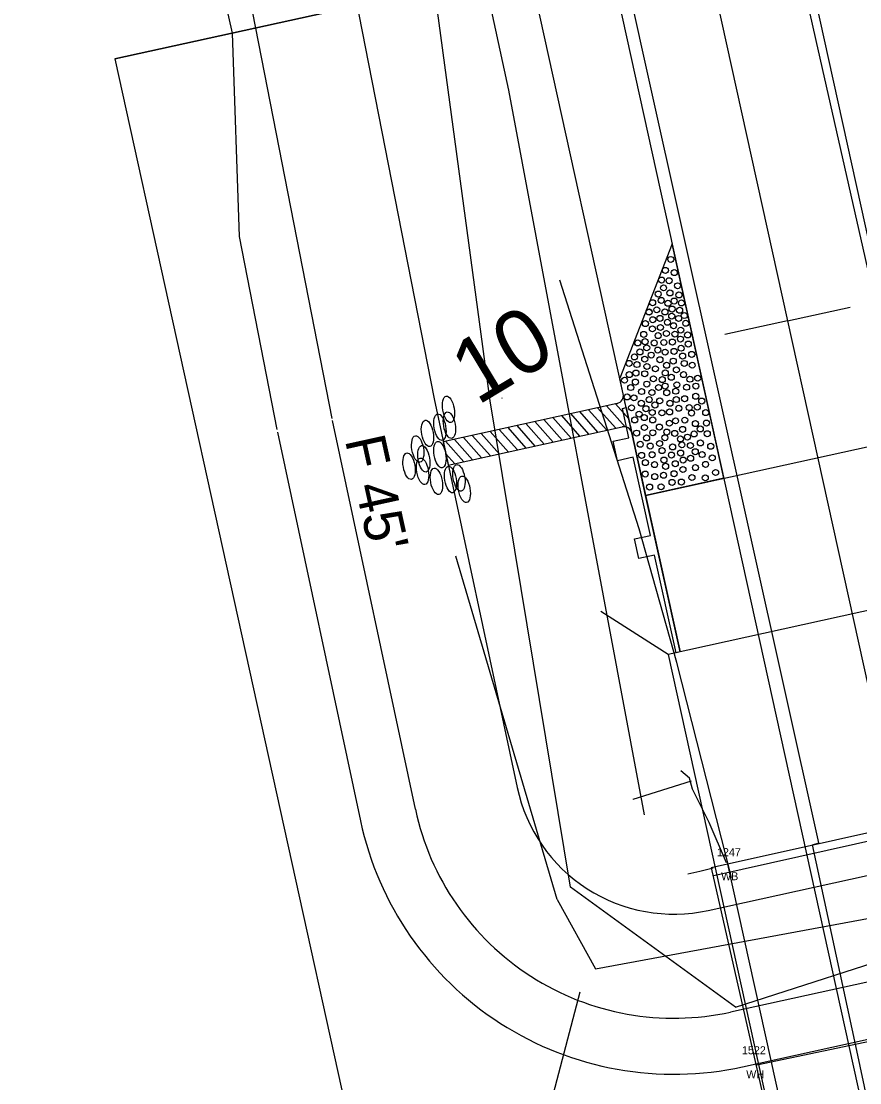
# Model space of a CAD drawing. Extents: x 2519952 to 2531965, y 848341 to 887632.
# Drawn here: x 2530852.7 to 2530957.4, y 852514.8 to 852647.4 of the extents above; entities that cross this region are included whole.
import ezdxf

# ---------------------------------------------------------------- set-up
doc = ezdxf.new("R2010")
doc.units = 0
for name, color, linetype in [('RD_EV_JW', 7, 'Continuous'), ('RD_EX_BldgApp', 7, 'Continuous'), ('RD_EX_BldgApp_txCode', 7, 'Continuous'), ('RD_EX_Bridge', 7, 'Continuous'), ('RD_EX_Conc', 7, 'Continuous'), ('RD_EX_DR_Pipe', 7, 'Continuous'), ('RD_EX_DV_Prop', 7, 'Continuous'), ('RD_EX_GuardRail', 7, 'Continuous'), ('RD_EX_H2O', 7, 'Continuous'), ('RD_EX_Misc', 7, 'Continuous'), ('RD_EX_Road', 7, 'Continuous'), ('RD_EX_RW', 7, 'Continuous'), ('RD_EX_VEG', 7, 'Continuous'), ('RD_HC_Cl', 7, 'Continuous'), ('RD_HC_Data_Tic', 7, 'Continuous'), ('RD_HC_TX_Sta50', 7, 'Continuous'), ('RD_PD_BCA', 7, 'Continuous'), ('RD_PD_Bridge', 7, 'Continuous'), ('RD_PD_CstnLmt', 7, 'Continuous'), ('RD_PD_DR_ErosCtrl', 7, 'Continuous'), ('RD_PD_Final_TrvlWay', 7, 'Continuous'), ('RD_PD_GR', 7, 'Continuous'), ('RD_PD_PaveShd', 7, 'Continuous'), ('RD_PD_RW', 7, 'Continuous'), ('RD_SMD_Locator', 7, 'Continuous')]:
    doc.layers.add(name, color=color, linetype=linetype)

# ---------------------------------------------------------------- blocks, each defined once
blk = doc.blocks.new('TBC1')
at = {"layer": 'RD_PD_GR'}
blk.add_lwpolyline([(12.5, 2.5), (15, 2.5), (15, 0.49), (25, 0.49), (25, 2.5), (27.5, 2.5), (27.5, 0.49), (31.25, 0.49), (31.25, 0), (0, 0), (0, 0.49), (12.5, 0.49)], close=True, dxfattribs=at)

msp = doc.modelspace()

# ---------------------------------------------------------------- linework, layer by layer
at = {"layer": 'RD_EV_JW'}
for points in [[(2530941.93, 852524.2), (2530921.34, 852539.21), (2530911.31, 852599.95), (2530891.36, 852747.65), (2530878.86, 852801.36), (2530855.69, 852888.8), (2530838.36, 852954.41), (2530821.58, 853001.04), (2530764.42, 853117.09), (2530719.97, 853083.34), (2530675.19, 853037.15)], [(2530941.93, 852524.2), (2530988.97, 852539.38), (2531002.68, 852568.81), (2530983.61, 852626.72), (2530958.57, 852695.74), (2530928.96, 852834.5), (2530911.44, 852907.05), (2530889.4, 853007.47), (2530879.48, 853052.19), (2530908.59, 853055.99), (2530938.06, 853061.93)]]:
    msp.add_lwpolyline(points, dxfattribs=at)
at = {"layer": 'RD_EX_BldgApp'}
msp.add_lwpolyline([(2530957.44, 852468.09), (2530949.04, 852505.48), (2530940.97, 852542.07)], dxfattribs=at)
at = {"layer": 'RD_EX_Bridge'}
for points in [[(2530955.67, 852467.77), (2531001.96, 852478), (2530985.83, 852552.07), (2530938.91, 852541.61), (2530955.67, 852467.77)], [(2530939.14, 852541.57), (2530937.47, 852541.16), (2530935.99, 852540.81)]]:
    msp.add_lwpolyline(points, dxfattribs=at)
at = {"layer": 'RD_EX_Conc'}
msp.add_lwpolyline([(2530940.81, 852542.25), (2530938.66, 852547.28), (2530936.57, 852551.45), (2530936.17, 852552.82), (2530935.11, 852553.74)], dxfattribs=at)
at = {"layer": 'RD_EX_DR_Pipe'}
msp.add_line((2530936.38, 852552.44), (2530929.1, 852550.16), dxfattribs=at)
at = {"layer": 'RD_EX_DV_Prop'}
for p, q in [((2530901.05, 852650.7), (2530864.42, 852642.64)), ((2530864.42, 852642.64), (2530928.94, 852349.66))]:
    msp.add_line(p, q, dxfattribs=at)
at = {"layer": 'RD_EX_GuardRail'}
for p, q in [((2530929.92, 852583.96), (2530920.01, 852615)), ((2530934.59, 852567.25), (2530929.92, 852583.96)), ((2530941.41, 852540.41), (2530934.59, 852567.25))]:
    msp.add_line(p, q, dxfattribs=at)
at = {"layer": 'RD_EX_H2O'}
msp.add_line((2530919.67, 852537.67), (2530907, 852580.53), dxfattribs=at)
for points in [[(2530919.67, 852537.67), (2530924.46, 852529.02), (2530997.12, 852542.46), (2531003.19, 852553.47), (2531007.69, 852596.79)], [(2530922.51, 852526.1), (2530912.95, 852489.75), (2530845.66, 852450.43), (2530795.63, 852412.19), (2530739.71, 852362.8), (2530741.39, 852332.59), (2530670.77, 852301.94)]]:
    msp.add_lwpolyline(points, dxfattribs=at)
at = {"layer": 'RD_EX_Misc'}
for p, q in [((2530939.22, 852540.64), (2530986.42, 852551.24)), ((2530991.48, 852526.75), (2530944.59, 852516.98))]:
    msp.add_line(p, q, dxfattribs=at)
at = {"layer": 'RD_EX_Road'}
for p, q in [((2530952, 852644.96), (2530932.11, 852735.09)), ((2530931.08, 852640.35), (2530910.78, 852730.8)), ((2530973.54, 852549.48), (2530952, 852644.96)), ((2530952.34, 852544.74), (2530931.08, 852640.35)), ((2530951.56, 852544.47), (2530952.34, 852544.74)), ((2530956.94, 852519.38), (2530951.56, 852544.47)), ((2530962.28, 852494.94), (2530956.94, 852519.38))]:
    msp.add_line(p, q, dxfattribs=at)
at = {"layer": 'RD_EX_RW'}
for q in [(2530901.05, 852650.7), (2530928.94, 852349.65)]:
    msp.add_line((2530864.42, 852642.64), q, dxfattribs=at)
at = {"layer": 'RD_EX_VEG'}
msp.add_lwpolyline([(2530930.57, 852548.23), (2530913.63, 852638.74), (2530872.38, 852829.12), (2530820.28, 852991.21)], dxfattribs=at)
at = {"layer": 'RD_HC_Cl'}
msp.add_line((2530821.93, 853184.38), (2531378.52, 850656.73), dxfattribs=at)
at = {"layer": 'RD_HC_Data_Tic'}
for q in [(2530956.24, 852611.65), (2530940.61, 852608.21)]:
    msp.add_line((2530948.42, 852609.93), q, dxfattribs=at)
at = {"layer": 'RD_PD_BCA'}
for p, q in [((2530879.07, 852645.86), (2530879.95, 852620.45)), ((2530879.95, 852620.45), (2530884.65, 852596.38)), ((2530884.72, 852596.03), (2530895.1, 852547.47))]:
    msp.add_line(p, q, dxfattribs=at)
msp.add_lwpolyline([(2530942.82, 852516.77), (2530991.6, 852527.51)], dxfattribs=at)
msp.add_arc((2530934.22, 852555.83), 40, 192.0677, 282.4185, dxfattribs=at)
at = {"layer": 'RD_PD_Bridge'}
for p, q in [((2530930.7, 852588.11), (2530973.67, 852597.58)), ((2530935, 852568.58), (2530930.7, 852588.11)), ((2530933.54, 852568.26), (2530925.11, 852573.65))]:
    msp.add_line(p, q, dxfattribs=at)
for points in [[(2530979.44, 852578.37), (2530933.54, 852568.26)], [(2530933.54, 852568.26), (2530961.49, 852441.3)]]:
    msp.add_lwpolyline(points, dxfattribs=at)
at = {"layer": 'RD_PD_CstnLmt'}
for p, q in [((2530885.11, 852698.39), (2530904.28, 852600.21)), ((2530904.28, 852600.21), (2530914.66, 852551.65))]:
    msp.add_line(p, q, dxfattribs=at)
msp.add_lwpolyline([(2530938.52, 852536.3), (2530987.3, 852547.04)], dxfattribs=at)
msp.add_arc((2530934.22, 852555.83), 20, 192.0677, 282.4185, dxfattribs=at)
at = {"layer": 'RD_PD_DR_ErosCtrl'}
for p, q in [((2530872.35, 852695.9), (2530891.52, 852597.72)), ((2530891.56, 852597.5), (2530901.94, 852548.93))]:
    msp.add_line(p, q, dxfattribs=at)
msp.add_lwpolyline([(2530941.31, 852523.61), (2530990.1, 852534.35)], dxfattribs=at)
msp.add_arc((2530934.22, 852555.83), 33, 192.0677, 282.4185, dxfattribs=at)
at = {"layer": 'RD_PD_Final_TrvlWay'}
for p, q in [((2530922.51, 852783.42), (2531196.7, 851538.25)), ((2530899.07, 852778.26), (2531173.26, 851533.09))]:
    msp.add_line(p, q, dxfattribs=at)
at = {"layer": 'RD_PD_GR'}
msp.add_line((2530928.28, 852599.1), (2530879.89, 852818.84), dxfattribs=at)
at = {"layer": 'RD_PD_PaveShd'}
for p, q in [((2530934.01, 852619.56), (2530927.47, 852602.76)), ((2530940.47, 852590.27), (2530934.01, 852619.56)), ((2530928.12, 852599.83), (2530927.47, 852602.76)), ((2530927.14, 852599.62), (2530905.43, 852594.82)), ((2530926.97, 852596.51), (2530924.7, 852599.08)), ((2530928.14, 852596.7), (2530925.82, 852599.33)), ((2530928.59, 852597.7), (2530926.93, 852599.57)), ((2530928.76, 852596.9), (2530928.12, 852599.83)), ((2530921.39, 852595.28), (2530919.12, 852597.85)), ((2530922.51, 852595.52), (2530920.23, 852598.09)), ((2530923.62, 852595.77), (2530921.35, 852598.34)), ((2530924.74, 852596.02), (2530922.47, 852598.59)), ((2530925.86, 852596.26), (2530923.58, 852598.83)), ((2530906.05, 852591.89), (2530927.79, 852596.69)), ((2530915.8, 852594.04), (2530913.53, 852596.61)), ((2530916.92, 852594.29), (2530914.65, 852596.86)), ((2530918.04, 852594.54), (2530915.76, 852597.11)), ((2530919.16, 852594.78), (2530916.88, 852597.35)), ((2530920.27, 852595.03), (2530918, 852597.6)), ((2530928.76, 852596.9), (2530930.7, 852588.11)), ((2530930.7, 852588.11), (2530928.76, 852596.9)), ((2530909.1, 852592.56), (2530906.83, 852595.13)), ((2530910.22, 852592.81), (2530907.95, 852595.38)), ((2530911.34, 852593.06), (2530909.06, 852595.63)), ((2530912.45, 852593.3), (2530910.18, 852595.87)), ((2530913.57, 852593.55), (2530911.3, 852596.12)), ((2530914.69, 852593.8), (2530912.41, 852596.37)), ((2530905.43, 852594.82), (2530906.05, 852591.89)), ((2530907.99, 852592.32), (2530905.71, 852594.89)), ((2530906.87, 852592.07), (2530905.74, 852593.34)), ((2530940.47, 852590.27), (2530930.7, 852588.11))]:
    msp.add_line(p, q, dxfattribs=at)
for centre in [(2530933.85, 852617.6), (2530933.85, 852617.6), (2530933.17, 852616.23), (2530933.17, 852616.23), (2530934.28, 852615.96), (2530934.28, 852615.96), (2530932.69, 852615.03), (2530932.69, 852615.03), (2530933.64, 852614.94), (2530933.64, 852614.94), (2530932.28, 852613.28), (2530932.94, 852614.05), (2530932.94, 852614.05), (2530933.74, 852613.42), (2530933.74, 852613.42), (2530934.69, 852614.31), (2530934.69, 852614.31), (2530931.58, 852612.2), (2530931.58, 852612.2), (2530932.65, 852612.48), (2530932.65, 852612.48), (2530933.5, 852612.12), (2530933.5, 852612.12), (2530934.27, 852612.4), (2530934.27, 852612.4), (2530934.87, 852613.16), (2530934.87, 852613.16), (2530935.18, 852612.16), (2530935.18, 852612.16), (2530931.13, 852611.01), (2530931.14, 852611.04), (2530932.1, 852611.31), (2530932.1, 852611.31), (2530933.12, 852611.04), (2530933.12, 852611.04), (2530934.01, 852611.4), (2530934.01, 852611.4), (2530934.95, 852611.25), (2530934.95, 852611.25), (2530935.53, 852610.59), (2530935.53, 852610.59), (2530930.68, 852609.58), (2530930.68, 852609.58), (2530931.6, 852610.07), (2530931.6, 852610.07), (2530932.5, 852610.24), (2530932.5, 852610.24), (2530933.43, 852609.75), (2530933.43, 852609.75), (2530933.96, 852610.52), (2530933.96, 852610.52), (2530934.19, 852609.32), (2530934.19, 852609.32), (2530934.82, 852610.23), (2530934.82, 852610.23), (2530935.72, 852609.63), (2530935.72, 852609.63), (2530930.47, 852608.24), (2530930.47, 852608.24), (2530931.55, 852608.93), (2530931.55, 852608.93), (2530932.27, 852608.09), (2530932.27, 852608.09), (2530932.55, 852609.1), (2530932.55, 852609.1), (2530933.3, 852608.35), (2530933.3, 852608.35), (2530934.37, 852608.27), (2530934.37, 852608.27), (2530935.1, 852608.77), (2530935.1, 852608.77), (2530935.95, 852608.17), (2530935.95, 852608.17), (2530929.72, 852607.17), (2530929.73, 852607.17), (2530930.64, 852607.33), (2530930.64, 852607.33), (2530931.78, 852607.17), (2530931.78, 852607.17), (2530932.98, 852607.23), (2530932.98, 852607.23), (2530934.05, 852607.28), (2530934.05, 852607.28), (2530935.06, 852607.65), (2530935.06, 852607.65), (2530936.03, 852607.03), (2530936.03, 852607.03), (2530929.31, 852605.42), (2530929.31, 852605.42), (2530930, 852606.05), (2530930, 852606.05), (2530930.84, 852606.56), (2530930.84, 852606.56), (2530931.4, 852605.65), (2530931.4, 852605.65), (2530932.23, 852606.28), (2530932.23, 852606.28), (2530933.14, 852606.02), (2530933.14, 852606.02), (2530934.25, 852606.12), (2530934.25, 852606.12), (2530935.14, 852606.51), (2530935.14, 852606.51), (2530935.33, 852605.53), (2530935.33, 852605.53), (2530936.46, 852605.74), (2530936.46, 852605.74), (2530928.65, 852604.62), (2530928.65, 852604.62), (2530929.62, 852604.47), (2530929.62, 852604.47), (2530930.59, 852605.14), (2530930.59, 852605.14), (2530930.87, 852604.23), (2530930.87, 852604.23), (2530932.49, 852605.08), (2530932.49, 852605.08), (2530933.33, 852604.38), (2530933.33, 852604.38), (2530934.16, 852604.9), (2530934.16, 852604.9), (2530935.53, 852604.61), (2530935.53, 852604.61), (2530936.52, 852604.39), (2530936.52, 852604.39), (2530928.67, 852603.21), (2530928.67, 852603.21), (2530929.5, 852603.41), (2530929.5, 852603.41), (2530930.59, 852603.32), (2530930.59, 852603.32), (2530931.67, 852602.69), (2530931.67, 852602.69), (2530931.92, 852603.94), (2530931.92, 852603.94), (2530933.16, 852603.43), (2530933.16, 852603.43), (2530933.91, 852602.88), (2530933.91, 852602.88), (2530934.55, 852603.81), (2530934.55, 852603.81), (2530935.44, 852603.21), (2530935.44, 852603.21), (2530936.24, 852602.64), (2530936.24, 852602.64), (2530937.21, 852602.77), (2530937.21, 852602.77), (2530928.07, 852602.52), (2530928.07, 852602.52), (2530928.07, 852602.52), (2530928.85, 852601.6), (2530928.85, 852601.6), (2530929.43, 852602.29), (2530929.43, 852602.29), (2530930.85, 852602.03), (2530930.85, 852602.03), (2530932.33, 852601.61), (2530932.33, 852601.61), (2530932.79, 852602.59), (2530932.79, 852602.59), (2530933.14, 852601.78), (2530933.14, 852601.78), (2530934.61, 852601.94), (2530934.61, 852601.94), (2530935.82, 852601.64), (2530935.82, 852601.64), (2530936.98, 852601.78), (2530936.98, 852601.78), (2530928.4, 852600.43), (2530928.4, 852600.43), (2530929.25, 852600.31), (2530929.25, 852600.31), (2530930.2, 852601.1), (2530930.2, 852601.1), (2530931.15, 852600.09), (2530931.15, 852600.09), (2530931.49, 852600.98), (2530931.49, 852600.98), (2530933.34, 852600.95), (2530933.34, 852600.95), (2530934.47, 852601.14), (2530934.47, 852601.14), (2530934.53, 852600.1), (2530934.53, 852600.1), (2530935.57, 852600.2), (2530935.57, 852600.2), (2530936.96, 852600.51), (2530936.96, 852600.51), (2530928.95, 852599.07), (2530928.95, 852599.07), (2530930.17, 852599.64), (2530930.17, 852599.64), (2530930.75, 852598.95), (2530930.75, 852598.95), (2530931.87, 852599.42), (2530931.87, 852599.42), (2530932.46, 852599.94), (2530932.46, 852599.94), (2530933.74, 852599.64), (2530933.74, 852599.64), (2530934.85, 852599.01), (2530934.85, 852599.01), (2530936.15, 852599.1), (2530936.15, 852599.1), (2530937.16, 852599.15), (2530937.16, 852599.15), (2530937.71, 852599.91), (2530929.34, 852597.55), (2530929.34, 852597.55), (2530929.89, 852598.28), (2530929.89, 852598.28), (2530930.54, 852597.84), (2530930.54, 852597.84), (2530931.54, 852598.48), (2530931.54, 852598.48), (2530931.59, 852597.55), (2530931.59, 852597.55), (2530932.74, 852598.44), (2530932.74, 852598.44), (2530933.7, 852598.55), (2530933.7, 852598.55), (2530934.44, 852597.44), (2530934.44, 852597.44), (2530935.6, 852597.53), (2530935.6, 852597.53), (2530936.44, 852598.41), (2530936.44, 852598.41), (2530938.21, 852598.47), (2530938.21, 852598.47), (2530930.55, 852596.61), (2530930.55, 852596.61), (2530932.43, 852596.66), (2530932.43, 852596.66), (2530933.35, 852596.04), (2530933.35, 852596.04), (2530933.67, 852597.15), (2530933.67, 852597.15), (2530935.33, 852596.37), (2530935.33, 852596.37), (2530936.92, 852597.09), (2530936.92, 852597.09), (2530937.53, 852596.43), (2530937.53, 852596.43), (2530938.3, 852597.17), (2530938.3, 852597.17), (2530929.58, 852595.91), (2530929.58, 852595.91), (2530930.83, 852595.3), (2530930.83, 852595.3), (2530931.6, 852595.95), (2530931.6, 852595.95), (2530933.11, 852595.33), (2530933.11, 852595.33), (2530934.34, 852595.88), (2530934.34, 852595.88), (2530935.06, 852595.18), (2530935.06, 852595.18), (2530935.93, 852595.41), (2530935.93, 852595.41), (2530936.76, 852595.81), (2530936.76, 852595.81), (2530937.54, 852594.68), (2530937.54, 852594.68), (2530938.4, 852595.83), (2530938.4, 852595.83), (2530930.03, 852594.51), (2530930.03, 852594.51), (2530931.28, 852594.29), (2530931.28, 852594.29), (2530932.45, 852594.61), (2530932.45, 852594.61), (2530932.76, 852593.72), (2530932.76, 852593.72), (2530934.08, 852594.18), (2530934.08, 852594.18), (2530935.08, 852593.42), (2530935.08, 852593.42), (2530935.23, 852594.44), (2530936.29, 852594.36), (2530936.29, 852594.36), (2530936.91, 852593.58), (2530936.91, 852593.58), (2530938.84, 852594.26), (2530938.84, 852594.26), (2530930.21, 852593.13), (2530930.21, 852593.13), (2530930.68, 852592.23), (2530930.68, 852592.23), (2530931.52, 852593.21), (2530931.52, 852593.21), (2530933, 852592.54), (2530933, 852592.54), (2530933.93, 852593.17), (2530933.93, 852593.17), (2530934.41, 852592.09), (2530934.41, 852592.09), (2530935.39, 852592.55), (2530935.39, 852592.55), (2530936.33, 852592.76), (2530936.33, 852592.76), (2530937.76, 852593.23), (2530937.76, 852593.23), (2530939.03, 852592.82), (2530939.03, 852592.82), (2530930.65, 852590.8), (2530930.65, 852590.8), (2530931.82, 852591.97), (2530931.82, 852591.97), (2530933.2, 852591.76), (2530933.2, 852591.76), (2530934.25, 852590.84), (2530934.25, 852590.84), (2530935.37, 852591.36), (2530935.37, 852591.36), (2530936.93, 852591.6), (2530936.93, 852591.6), (2530938.19, 852592), (2530938.19, 852592), (2530939.45, 852590.99), (2530939.45, 852590.99), (2530931.84, 852590.48), (2530931.84, 852590.48), (2530932.94, 852590.64), (2530932.94, 852590.64), (2530934.01, 852589.76), (2530934.01, 852589.76), (2530935.17, 852589.8), (2530935.17, 852589.8), (2530936.49, 852590.36), (2530936.49, 852590.36), (2530938.15, 852590.32), (2530938.15, 852590.32), (2530931.2, 852589.17), (2530931.2, 852589.17), (2530931.2, 852589.17), (2530932.63, 852589.2), (2530932.63, 852589.2)]:
    msp.add_circle(centre, 0.375, dxfattribs=at)
for centre, start, end in [((2530926.93, 852600.6), 282.4481, 12.4185), ((2530928, 852595.71), 12.4185, 102.4481)]:
    msp.add_arc(centre, 1, start, end, dxfattribs=at)
for centre in [(2530906.09, 852598.88), (2530905.02, 852596.65), (2530905.02, 852596.65), (2530906.2, 852596.9), (2530903.46, 852595.87), (2530903.46, 852595.87), (2530902.24, 852593.93), (2530902.24, 852593.93), (2530903.01, 852592.7), (2530903.01, 852592.7), (2530905.02, 852593.23), (2530905.02, 852593.23), (2530901.16, 852591.78), (2530901.16, 852591.78), (2530902.86, 852591.14), (2530902.86, 852591.14), (2530904.58, 852589.88), (2530904.58, 852589.88), (2530906.34, 852590.11), (2530906.34, 852590.11), (2530907.4, 852590.32), (2530907.4, 852590.32), (2530908.06, 852588.89), (2530908.06, 852588.89)]:
    msp.add_ellipse(centre, major_axis=(-0.29, 1.65), ratio=0.429445, dxfattribs=at)
at = {"layer": 'RD_PD_RW'}
msp.add_line((2530830.69, 852865.6), (2530879.07, 852645.86), dxfattribs=at)
at = {"layer": 'RD_SMD_Locator'}
for centre in [(2530952, 852644.96), (2530931.08, 852640.35), (2530913.63, 852638.74), (2530920.01, 852615), (2530912.77, 852600.27), (2530929.92, 852583.96), (2530907, 852580.53), (2530934.59, 852567.25), (2530935.11, 852553.74), (2530936.17, 852552.82), (2530936.38, 852552.44), (2530936.57, 852551.45), (2530929.1, 852550.16), (2530930.57, 852548.23), (2530938.66, 852547.28), (2530952.34, 852544.74), (2530951.56, 852544.47), (2530940.81, 852542.25), (2530940.97, 852542.07), (2530935.99, 852540.81), (2530937.47, 852541.16), (2530938.91, 852541.61), (2530939.14, 852541.57), (2530939.22, 852540.64), (2530941.41, 852540.41), (2530921.34, 852539.21), (2530919.67, 852537.67), (2530919.67, 852537.67), (2530924.46, 852529.02), (2530922.51, 852526.1), (2530941.93, 852524.2), (2530941.93, 852524.2), (2530956.94, 852519.38), (2530944.09, 852517.33), (2530944.59, 852516.98)]:
    msp.add_circle(centre, 0.001, dxfattribs=at)

# ---------------------------------------------------------------- block references
at = {"layer": 'RD_PD_Bridge', "rotation": 102.41848259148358}
msp.add_blockref('TBC1', (2530935, 852568.58), dxfattribs=at)

# ---------------------------------------------------------------- texts
at = {"layer": 'RD_EX_BldgApp_txCode'}
for s, p in [('1247', (2530939.62, 852543.07)), ('WB', (2530940.13, 852540.07)), ('1522', (2530942.74, 852518.33)), ('WH', (2530943.27, 852515.33))]:
    msp.add_text(s, height=1, dxfattribs=at).set_placement(p)
at = {"layer": 'RD_HC_TX_Sta50'}
msp.add_text('10', height=8, rotation=31.1184, dxfattribs=at).set_placement((2530909.68, 852599.29))
at = {"layer": 'RD_PD_CstnLmt'}
msp.add_text("F 45'", height=5, rotation=282.4185, dxfattribs=at).set_placement((2530893.14, 852595.07))

doc.saveas('drawing.dxf')
